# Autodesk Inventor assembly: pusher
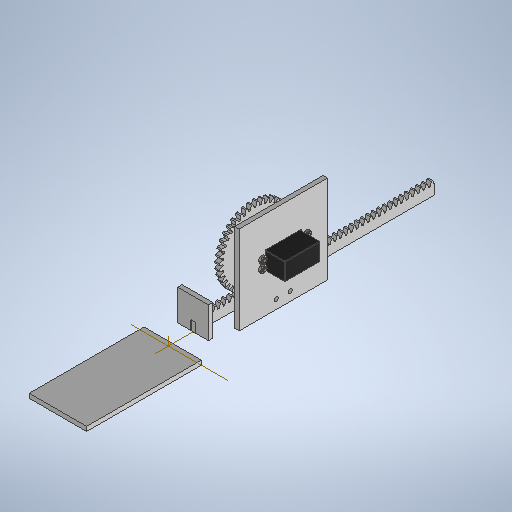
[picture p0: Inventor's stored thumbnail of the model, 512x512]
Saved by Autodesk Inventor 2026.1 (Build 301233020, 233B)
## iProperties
Created: 2026-10
Part Number: pusher
Document SubType Name: Assembly
Designer: alolo
Author: alolo
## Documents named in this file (9)
- C:\Users\hp\Documents\Inventor\DOM1_CartesianRobot\pusher.iam
- C:\Users\hp\Documents\Inventor\DOM1_CartesianRobot\pusher_pinion.ipt
- C:\Users\hp\Documents\Inventor\DOM1_CartesianRobot\Servo MG996R.ipt
- C:\Users\hp\Documents\Inventor\DOM1_CartesianRobot\pusher_rack.ipt
- C:\Users\hp\Documents\Inventor\DOM1_CartesianRobot\pusher_base.ipt
- C:\Users\hp\Documents\Inventor\DOM1_CartesianRobot\pusher_support.ipt
- C:\Users\hp\Documents\Inventor\DOM1_CartesianRobot\pusher_punch.ipt
- C:\Users\hp\Documents\Inventor\Content Center Files\R2026\en-US\ISO 4017(1)\ISO 4017 - M4 x 12 - ISO.ipt
- C:\Users\hp\Documents\Inventor\Content Center Files\R2026\en-US\ISO 4032(2)\ISO 4032 - M4 - ISO.ipt
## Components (14 placed, 8 different names)
1. Servo MG996R:1
2. pusher_base:1 — Mate:1, Mate:2, Mate:11, Slider:2, Flush:2, Mate:14
3. pusher_support
4. pusher_pinion:1 — Rotational:1, Rotation/Translation:1, Flush:1
5. pusher_rack:1 — Slider:2, Rotation/Translation:1, Mate:12, Flush:1, Flush:3, Mate:31
6. pusher_punch:2 — Mate:12, Mate:14, Flush:3, Mate:31
7. ISO 4017 M4 x 12:1 — Mate:15, Mate:16
8. ISO 4032 M4:1 — Mate:23, Mate:24
9. ISO 4017 M4 x 12:2 — Mate:17, Mate:18
10. ISO 4017 M4 x 12:3 — Mate:19, Mate:20
11. ISO 4017 M4 x 12:4 — Mate:21, Mate:22
12. ISO 4032 M4:2 — Mate:25, Mate:26
13. ISO 4032 M4:3 — Mate:27, Mate:28
14. ISO 4032 M4:4 — Mate:29, Mate:30
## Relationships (28: Mate 22, Flush 3, RevoluteJoint 1, TranslationJoint 1, RelateRotateTranslate 1)
- Mate:1: pusher_base:1
- Mate:2: pusher_base:1
- Rotational:1 [RevoluteJoint]: pusher_pinion:1
- Mate:11: pusher_base:1
- Slider:2 [TranslationJoint]: pusher_base:1 ↔ pusher_rack:1
- Rotation/Translation:1 [RelateRotateTranslate]: pusher_pinion:1 ↔ pusher_rack:1
- Mate:12: pusher_rack:1 ↔ pusher_punch:2
- Flush:1: pusher_pinion:1 ↔ pusher_rack:1
- Flush:2: pusher_base:1
- Mate:14: pusher_base:1 ↔ pusher_punch:2
- Mate:15: ISO 4017 M4 x 12:1
- Mate:16: ISO 4017 M4 x 12:1
- Mate:17: ISO 4017 M4 x 12:2
- Mate:18: ISO 4017 M4 x 12:2
- Mate:19: ISO 4017 M4 x 12:3
- Mate:20: ISO 4017 M4 x 12:3
- Mate:21: ISO 4017 M4 x 12:4
- Mate:22: ISO 4017 M4 x 12:4
- Mate:23: ISO 4032 M4:1
- Mate:24: ISO 4032 M4:1
- Mate:25: ISO 4032 M4:2
- Mate:26: ISO 4032 M4:2
- Mate:27: ISO 4032 M4:3
- Mate:28: ISO 4032 M4:3
- Mate:29: ISO 4032 M4:4
- Mate:30: ISO 4032 M4:4
- Flush:3: pusher_rack:1 ↔ pusher_punch:2
- Mate:31: pusher_rack:1 ↔ pusher_punch:2
